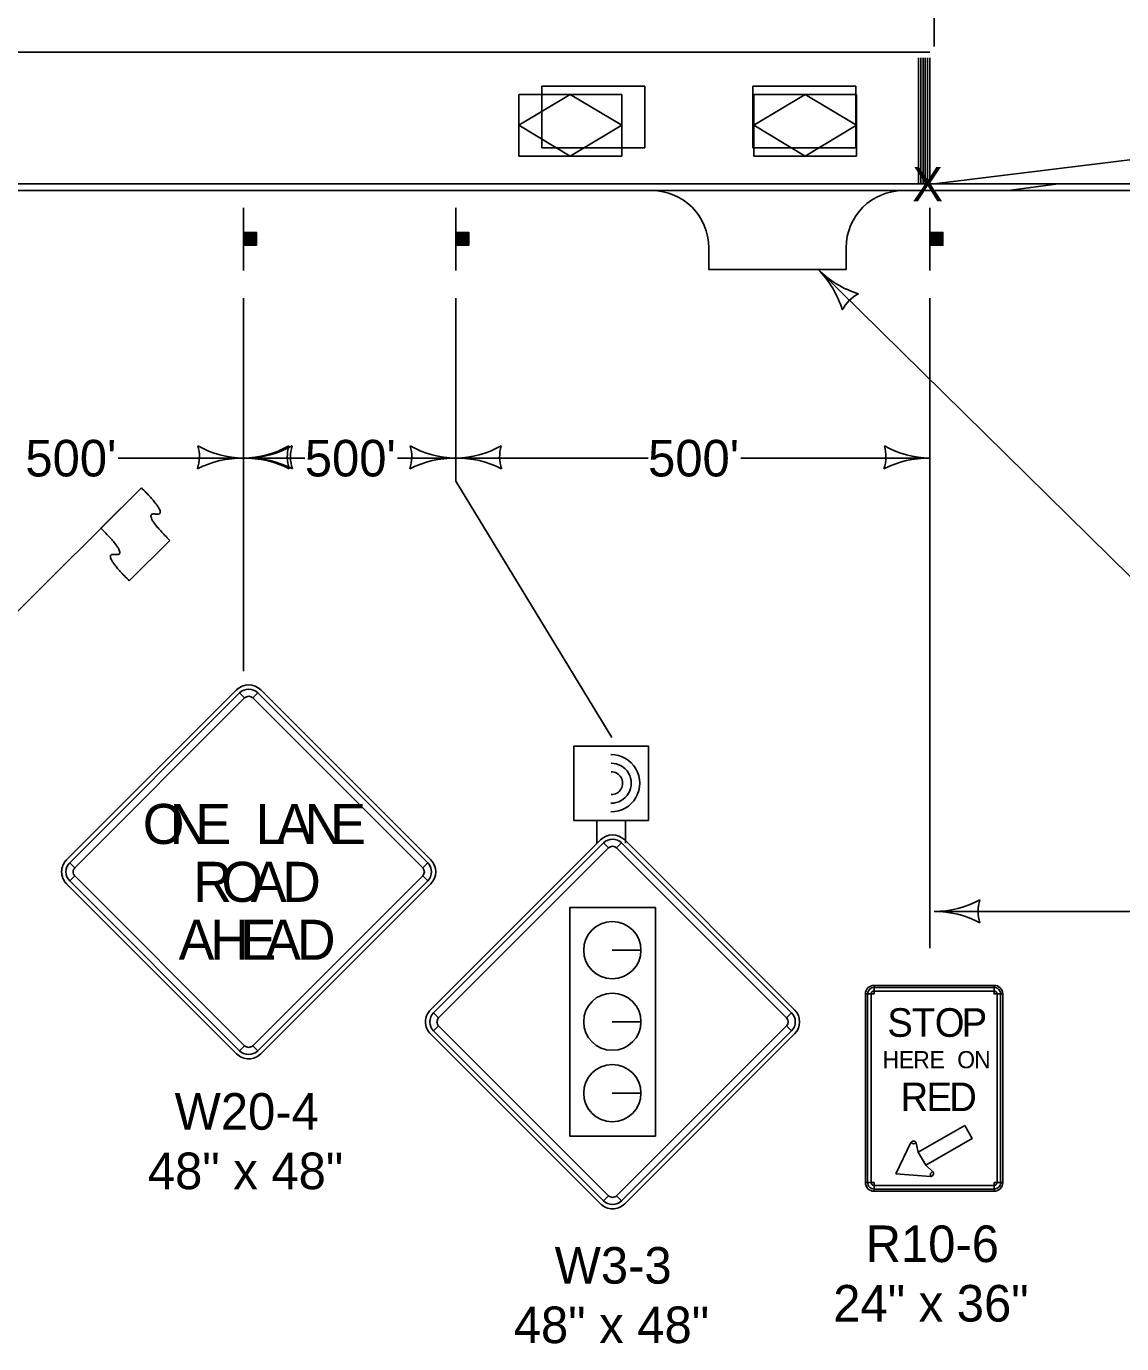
# Model space of a CAD drawing. Extents: x -2134934 to -2122394, y -2140205 to -2137036.
# Drawn here: x -2129927 to -2129448, y -2138172 to -2137596 of the extents above; entities that cross this region are included whole.
import ezdxf

# ---------------------------------------------------------------- set-up
doc = ezdxf.new("R2010")
doc.units = 0
for name, color, linetype in [('Barrier', 7, 'Continuous'), ('BridgeSuperStructureExisting', 7, 'Continuous'), ('DsnShtPlotIdentification', 7, 'Continuous'), ('DsnShtPlotShape', 7, 'Continuous'), ('dsnTextFinalPlan', 7, 'Continuous'), ('TC_Barrier', 7, 'Continuous')]:
    doc.layers.add(name, color=color, linetype=linetype)

msp = doc.modelspace()

# ---------------------------------------------------------------- linework, layer by layer
at = {"layer": 'Barrier'}
for p, q in [((-2129933.82, -2137855.42), (-2129876.5, -2137798.11)), ((-2129876.5, -2137798.11), (-2129894.18, -2137815.79)), ((-2129881.8, -2137838.78), (-2129864.12, -2137821.1)), ((-2129834.91, -2137886.48), (-2129909.16, -2137960.72)), ((-2129750.06, -2137960.72), (-2129824.31, -2137886.48)), ((-2129833.59, -2137887.8), (-2129831.38, -2137890.01)), ((-2129827.84, -2137890.01), (-2129825.63, -2137887.8)), ((-2129675.93, -2137952.07), (-2129750.18, -2138026.31)), ((-2129674.61, -2137953.39), (-2129672.4, -2137955.6)), ((-2129668.86, -2137955.6), (-2129666.65, -2137953.39)), ((-2129591.08, -2138026.31), (-2129665.32, -2137952.07)), ((-2129905.62, -2137964.26), (-2129907.83, -2137962.05)), ((-2129751.39, -2137962.05), (-2129753.59, -2137964.26)), ((-2129907.83, -2137970.01), (-2129905.62, -2137967.8)), ((-2129753.59, -2137967.8), (-2129751.39, -2137970.01)), ((-2129909.16, -2137971.33), (-2129834.91, -2138045.58)), ((-2129824.31, -2138045.58), (-2129750.06, -2137971.33)), ((-2129658.22, -2138000.29), (-2129670.72, -2138000.29)), ((-2129670.72, -2138000.29), (-2129658.22, -2138000.29)), ((-2129560.12, -2138019.4), (-2129556.37, -2138019.4)), ((-2129559.18, -2138019.4), (-2129557.62, -2138019.4)), ((-2129556.37, -2138019.4), (-2129556.37, -2138015.65)), ((-2129556.37, -2138018.15), (-2129556.37, -2138016.58)), ((-2129503.87, -2138015.65), (-2129503.87, -2138019.4)), ((-2129503.87, -2138016.58), (-2129503.87, -2138018.15)), ((-2129503.87, -2138019.4), (-2129500.12, -2138019.4)), ((-2129502.62, -2138019.4), (-2129501.05, -2138019.4)), ((-2129746.64, -2138029.85), (-2129748.85, -2138027.64)), ((-2129658.22, -2138031.54), (-2129670.72, -2138031.54)), ((-2129670.72, -2138031.54), (-2129658.22, -2138031.54)), ((-2129592.41, -2138027.64), (-2129594.61, -2138029.85)), ((-2129750.18, -2138036.92), (-2129675.93, -2138111.16)), ((-2129748.85, -2138035.59), (-2129746.64, -2138033.38)), ((-2129665.32, -2138111.16), (-2129591.08, -2138036.92)), ((-2129594.61, -2138033.38), (-2129592.41, -2138035.59)), ((-2129831.38, -2138042.04), (-2129833.59, -2138044.25)), ((-2129825.63, -2138044.25), (-2129827.84, -2138042.04)), ((-2129658.22, -2138062.79), (-2129670.72, -2138062.79)), ((-2129670.72, -2138062.79), (-2129658.22, -2138062.79)), ((-2129540.26, -2138084.38), (-2129539.15, -2138084.96)), ((-2129539.15, -2138084.96), (-2129537.93, -2138084.69)), ((-2129531.65, -2138097.95), (-2129531.7, -2138099.2)), ((-2129530.8, -2138097.03), (-2129531.65, -2138097.95)), ((-2129556.37, -2138101.9), (-2129560.12, -2138101.9)), ((-2129557.62, -2138101.9), (-2129559.18, -2138101.9)), ((-2129556.37, -2138105.65), (-2129556.37, -2138101.9)), ((-2129556.37, -2138104.71), (-2129556.37, -2138103.15)), ((-2129500.12, -2138101.9), (-2129503.87, -2138101.9)), ((-2129503.87, -2138101.9), (-2129503.87, -2138105.65)), ((-2129503.87, -2138103.15), (-2129503.87, -2138104.71)), ((-2129501.05, -2138101.9), (-2129502.62, -2138101.9)), ((-2129672.4, -2138107.63), (-2129674.61, -2138109.84)), ((-2129666.65, -2138109.84), (-2129668.86, -2138107.63))]:
    msp.add_line(p, q, dxfattribs=at)
for points in [[(-2129833.59, -2137887.8), (-2129907.83, -2137962.05), (-2129905.62, -2137964.26), (-2129831.38, -2137890.01), (-2129833.59, -2137887.8)], [(-2129751.39, -2137962.05), (-2129825.63, -2137887.8), (-2129827.84, -2137890.01), (-2129753.59, -2137964.26), (-2129751.39, -2137962.05)], [(-2129674.61, -2137953.39), (-2129748.85, -2138027.64), (-2129746.64, -2138029.85), (-2129672.4, -2137955.6), (-2129674.61, -2137953.39)], [(-2129592.41, -2138027.64), (-2129666.65, -2137953.39), (-2129668.86, -2137955.6), (-2129594.61, -2138029.85), (-2129592.41, -2138027.64)], [(-2129907.83, -2137970.01), (-2129833.59, -2138044.25), (-2129831.38, -2138042.04), (-2129905.62, -2137967.8), (-2129907.83, -2137970.01)], [(-2129825.63, -2138044.25), (-2129751.39, -2137970.01), (-2129753.59, -2137967.8), (-2129827.84, -2138042.04), (-2129825.63, -2138044.25)], [(-2129651.9, -2137981.67), (-2129689.36, -2137981.67), (-2129689.36, -2138081.56), (-2129651.9, -2138081.56), (-2129651.9, -2137981.67)], [(-2129556.37, -2138105.65), (-2129503.87, -2138105.65), (-2129503.87, -2138101.9), (-2129500.12, -2138101.9), (-2129500.12, -2138019.4), (-2129503.87, -2138019.4), (-2129503.87, -2138015.65), (-2129556.37, -2138015.65), (-2129556.37, -2138019.4), (-2129560.12, -2138019.4), (-2129560.12, -2138101.9), (-2129556.37, -2138101.9), (-2129556.37, -2138105.65)], [(-2129557.62, -2138019.4), (-2129557.62, -2138101.9), (-2129559.18, -2138101.9), (-2129559.18, -2138019.4), (-2129557.62, -2138019.4)], [(-2129503.87, -2138018.15), (-2129556.37, -2138018.15), (-2129556.37, -2138016.58), (-2129503.87, -2138016.58), (-2129503.87, -2138018.15)], [(-2129502.62, -2138101.9), (-2129502.62, -2138019.4), (-2129501.05, -2138019.4), (-2129501.05, -2138101.9), (-2129502.62, -2138101.9)], [(-2129748.85, -2138035.59), (-2129674.61, -2138109.84), (-2129672.4, -2138107.63), (-2129746.64, -2138033.38), (-2129748.85, -2138035.59)], [(-2129666.65, -2138109.84), (-2129592.41, -2138035.59), (-2129594.61, -2138033.38), (-2129668.86, -2138107.63), (-2129666.65, -2138109.84)], [(-2129516.74, -2138076.9), (-2129513.46, -2138082.58), (-2129533.77, -2138094.3), (-2129537.05, -2138088.62), (-2129516.74, -2138076.9)], [(-2129546.77, -2138098.02), (-2129531.7, -2138099.2), (-2129531.65, -2138097.95), (-2129530.8, -2138097.03), (-2129533.77, -2138094.3), (-2129537.05, -2138088.62), (-2129537.93, -2138084.69), (-2129539.15, -2138084.96), (-2129540.26, -2138084.38), (-2129546.77, -2138098.02)], [(-2129556.37, -2138103.15), (-2129503.87, -2138103.15), (-2129503.87, -2138104.71), (-2129556.37, -2138104.71), (-2129556.37, -2138103.15)]]:
    msp.add_lwpolyline(points, close=True, dxfattribs=at)
for centre in [(-2129670.72, -2138000.29), (-2129670.72, -2138031.54), (-2129670.72, -2138062.79)]:
    msp.add_circle(centre, 12.5, dxfattribs=at)
for centre, radius, start, end in [((-2129829.61, -2137891.78), 7.5, 44.99999, 134.99974), ((-2129829.61, -2137891.78), 5.62, 44.99999, 134.99974), ((-2129829.61, -2137891.78), 2.5, 44.99999, 134.99974), ((-2129670.63, -2137957.37), 7.5, 44.99999, 134.99974), ((-2129670.63, -2137957.37), 5.62, 44.99999, 134.99974), ((-2129670.63, -2137957.37), 2.5, 44.99999, 134.99974), ((-2129903.85, -2137966.03), 7.5, 134.99974, 224.99995), ((-2129903.85, -2137966.03), 5.62, 134.99974, 224.99995), ((-2129755.36, -2137966.03), 5.62, 315.00016, 44.9998), ((-2129755.36, -2137966.03), 7.5, 315.00016, 44.9998), ((-2129903.85, -2137966.03), 2.5, 134.99974, 224.99995), ((-2129755.36, -2137966.03), 2.5, 315.00016, 44.9998), ((-2129556.37, -2138019.4), 3.75, 90.00021, 179.99985), ((-2129556.37, -2138019.4), 2.81, 90.00021, 179.99985), ((-2129556.37, -2138019.4), 1.25, 90.00021, 179.99985), ((-2129503.87, -2138019.4), 3.75, 0, 90.00021), ((-2129503.87, -2138019.4), 2.81, 0, 90.00021), ((-2129503.87, -2138019.4), 1.25, 0, 90.00021), ((-2129744.87, -2138031.62), 7.5, 134.99974, 224.99995), ((-2129744.87, -2138031.62), 5.62, 134.99974, 224.99995), ((-2129744.87, -2138031.62), 2.5, 134.99974, 224.99995), ((-2129596.38, -2138031.62), 2.5, 315.00016, 44.9998), ((-2129596.38, -2138031.62), 5.62, 315.00016, 44.9998), ((-2129596.38, -2138031.62), 7.5, 315.00016, 44.9998), ((-2129829.61, -2138040.27), 2.5, 224.99995, 315.00016), ((-2129829.61, -2138040.27), 7.5, 224.99995, 315.00016), ((-2129829.61, -2138040.27), 5.62, 224.99995, 315.00016), ((-2129539.15, -2138084.96), 1.25, 12.62232, 152.27557), ((-2129531.65, -2138097.95), 1.25, 267.72427, 47.37758), ((-2129556.37, -2138101.9), 3.75, 179.99985, 270.00006), ((-2129556.37, -2138101.9), 2.81, 179.99985, 270.00006), ((-2129556.37, -2138101.9), 1.25, 179.99985, 270.00006), ((-2129503.87, -2138101.9), 3.75, 270.00006, 0.00027), ((-2129503.87, -2138101.9), 2.81, 270.00006, 0.00027), ((-2129503.87, -2138101.9), 1.25, 270.00006, 0.00027), ((-2129670.63, -2138105.86), 7.5, 224.99995, 315.00016), ((-2129670.63, -2138105.86), 5.62, 224.99995, 315.00016), ((-2129670.63, -2138105.86), 2.5, 224.99995, 315.00016)]:
    msp.add_arc(centre, radius, start, end, dxfattribs=at)
for points in [[(-2129864.12, -2137821.1), (-2129876.5, -2137808.72), (-2129864.12, -2137810.49), (-2129876.5, -2137798.11)], [(-2129894.18, -2137815.79), (-2129881.8, -2137828.17), (-2129894.17, -2137826.4), (-2129881.8, -2137838.78)]]:
    msp.add_open_spline(points, degree=2, dxfattribs=at)
at = {"layer": 'BridgeSuperStructureExisting'}
for p, q in [((-2129530.12, -2137367.55), (-2129530.12, -2137605.16)), ((-2129530.12, -2137665.16), (-2129039.8, -2137605.17)), ((-2129536.95, -2137665.16), (-2129536.95, -2137610.16)), ((-2129535.95, -2137665.16), (-2129535.95, -2137610.16)), ((-2129534.95, -2137665.16), (-2129534.95, -2137610.16)), ((-2129533.95, -2137665.16), (-2129533.95, -2137610.16)), ((-2129532.95, -2137665.16), (-2129532.95, -2137610.16)), ((-2129531.95, -2137665.16), (-2129531.95, -2137610.16)), ((-2129701.47, -2137622.46), (-2129656.47, -2137622.46)), ((-2129701.47, -2137649.46), (-2129701.47, -2137622.46)), ((-2129656.47, -2137622.46), (-2129701.47, -2137622.46)), ((-2129701.47, -2137622.46), (-2129701.47, -2137649.46)), ((-2129656.47, -2137622.46), (-2129656.47, -2137649.46)), ((-2129656.47, -2137649.46), (-2129656.47, -2137622.46)), ((-2129609.28, -2137622.54), (-2129564.28, -2137622.54)), ((-2129609.28, -2137649.54), (-2129609.28, -2137622.54)), ((-2129564.28, -2137622.54), (-2129609.28, -2137622.54)), ((-2129609.28, -2137622.54), (-2129609.28, -2137649.54)), ((-2129564.28, -2137622.54), (-2129564.28, -2137649.54)), ((-2129564.28, -2137649.54), (-2129564.28, -2137622.54)), ((-2129711.63, -2137653.13), (-2129711.63, -2137626.13)), ((-2129711.63, -2137626.13), (-2129666.63, -2137626.13)), ((-2129666.63, -2137653.13), (-2129666.63, -2137626.13)), ((-2129608.95, -2137653.13), (-2129608.95, -2137626.13)), ((-2129608.95, -2137626.13), (-2129563.95, -2137626.13)), ((-2129563.95, -2137653.13), (-2129563.95, -2137626.13)), ((-2129656.47, -2137649.46), (-2129701.47, -2137649.46)), ((-2129701.47, -2137649.46), (-2129656.47, -2137649.46)), ((-2129564.28, -2137649.54), (-2129609.28, -2137649.54)), ((-2129609.28, -2137649.54), (-2129564.28, -2137649.54)), ((-2129711.63, -2137653.13), (-2129666.63, -2137653.13)), ((-2129608.95, -2137653.13), (-2129563.95, -2137653.13)), ((-2130182.57, -2137665.16), (-2128870.12, -2137665.16)), ((-2129543.56, -2137668.16), (-2129653.56, -2137668.16)), ((-2129639.46, -2137668.16), (-2129614.46, -2137668.16)), ((-2129831.95, -2137675.66), (-2129831.95, -2137703.16)), ((-2129739.15, -2137675.66), (-2129739.15, -2137703.16)), ((-2129531.95, -2137675.66), (-2129531.95, -2137703.16)), ((-2129831.54, -2137692.11), (-2129831.54, -2137686.52)), ((-2129831.26, -2137686.52), (-2129831.26, -2137692.11)), ((-2129830.99, -2137692.11), (-2129830.99, -2137686.52)), ((-2129830.73, -2137686.52), (-2129830.73, -2137692.11)), ((-2129830.51, -2137692.11), (-2129830.51, -2137686.52)), ((-2129830.3, -2137686.52), (-2129830.3, -2137692.11)), ((-2129829.96, -2137692.11), (-2129829.96, -2137686.52)), ((-2129829.7, -2137686.52), (-2129829.7, -2137692.11)), ((-2129829.47, -2137692.11), (-2129829.49, -2137686.52)), ((-2129829.16, -2137686.52), (-2129829.16, -2137692.11)), ((-2129828.78, -2137692.11), (-2129828.78, -2137686.52)), ((-2129828.35, -2137686.52), (-2129828.35, -2137692.11)), ((-2129828.12, -2137692.11), (-2129828.14, -2137686.52)), ((-2129827.71, -2137686.52), (-2129827.69, -2137692.11)), ((-2129827.49, -2137692.11), (-2129827.49, -2137686.52)), ((-2129827.17, -2137686.52), (-2129827.17, -2137692.11)), ((-2129826.94, -2137692.11), (-2129826.94, -2137686.52)), ((-2129826.62, -2137686.52), (-2129826.62, -2137692.11)), ((-2129738.74, -2137692.11), (-2129738.74, -2137686.52)), ((-2129738.46, -2137686.52), (-2129738.46, -2137692.11)), ((-2129738.2, -2137692.11), (-2129738.2, -2137686.52)), ((-2129737.93, -2137686.52), (-2129737.93, -2137692.11)), ((-2129737.71, -2137692.11), (-2129737.71, -2137686.52)), ((-2129737.5, -2137686.52), (-2129737.5, -2137692.11)), ((-2129737.16, -2137692.11), (-2129737.16, -2137686.52)), ((-2129736.9, -2137686.52), (-2129736.9, -2137692.11)), ((-2129736.68, -2137692.11), (-2129736.7, -2137686.52)), ((-2129736.36, -2137686.52), (-2129736.36, -2137692.11)), ((-2129735.98, -2137692.11), (-2129735.98, -2137686.52)), ((-2129735.55, -2137686.52), (-2129735.55, -2137692.11)), ((-2129735.33, -2137692.11), (-2129735.35, -2137686.52)), ((-2129734.91, -2137686.52), (-2129734.9, -2137692.11)), ((-2129734.69, -2137692.11), (-2129734.69, -2137686.52)), ((-2129734.37, -2137686.52), (-2129734.37, -2137692.11)), ((-2129734.15, -2137692.11), (-2129734.15, -2137686.52)), ((-2129733.83, -2137686.52), (-2129733.83, -2137692.11)), ((-2129531.54, -2137692.11), (-2129531.54, -2137686.52)), ((-2129531.26, -2137686.52), (-2129531.26, -2137692.11)), ((-2129530.99, -2137692.11), (-2129530.99, -2137686.52)), ((-2129530.73, -2137686.52), (-2129530.73, -2137692.11)), ((-2129530.51, -2137692.11), (-2129530.51, -2137686.52)), ((-2129530.3, -2137686.52), (-2129530.3, -2137692.11)), ((-2129529.96, -2137692.11), (-2129529.96, -2137686.52)), ((-2129529.7, -2137686.52), (-2129529.7, -2137692.11)), ((-2129529.48, -2137692.11), (-2129529.49, -2137686.52)), ((-2129529.16, -2137686.52), (-2129529.16, -2137692.11)), ((-2129528.78, -2137692.11), (-2129528.78, -2137686.52)), ((-2129528.35, -2137686.52), (-2129528.35, -2137692.11)), ((-2129528.13, -2137692.11), (-2129528.14, -2137686.52)), ((-2129527.71, -2137686.52), (-2129527.69, -2137692.11)), ((-2129527.49, -2137692.11), (-2129527.49, -2137686.52)), ((-2129527.17, -2137686.52), (-2129527.17, -2137692.11)), ((-2129526.94, -2137692.11), (-2129526.94, -2137686.52)), ((-2129526.63, -2137686.52), (-2129526.63, -2137692.11)), ((-2129366.79, -2137913.4), (-2129580.78, -2137702.65)), ((-2129831.95, -2137878.33), (-2129831.95, -2137715.16)), ((-2129739.15, -2137795.16), (-2129739.15, -2137715.16)), ((-2129531.95, -2137999.46), (-2129531.95, -2137715.16)), ((-2129886.7, -2137785.16), (-2129831.95, -2137785.16)), ((-2129830.55, -2137785.16), (-2129805.1, -2137785.16)), ((-2129764.6, -2137785.16), (-2129739.15, -2137785.16)), ((-2129739.15, -2137785.16), (-2129655.1, -2137785.16)), ((-2129614.6, -2137785.16), (-2129531.95, -2137785.16)), ((-2129739.15, -2137795.16), (-2129670.96, -2137907.34)), ((-2129677.47, -2137943.52), (-2129677.47, -2137953.52)), ((-2129664.97, -2137943.52), (-2129664.97, -2137953.52)), ((-2128866.54, -2137983.33), (-2129530.12, -2137983.33))]:
    msp.add_line(p, q, dxfattribs=at)
for points in [[(-2129831.86, -2137692.11), (-2129831.86, -2137686.48), (-2129826.23, -2137686.48), (-2129826.23, -2137692.11)], [(-2129739.06, -2137692.11), (-2129739.06, -2137686.48), (-2129733.43, -2137686.48), (-2129733.43, -2137692.11)], [(-2129531.86, -2137692.11), (-2129531.86, -2137686.48), (-2129526.23, -2137686.48), (-2129526.23, -2137692.11)], [(-2129687.47, -2137943.52), (-2129687.47, -2137911.02), (-2129654.97, -2137911.02), (-2129654.97, -2137943.52)]]:
    msp.add_lwpolyline(points, close=True, dxfattribs=at)
msp.add_lwpolyline([(-2129628.56, -2137693.16), (-2129628.56, -2137702.65), (-2129568.56, -2137702.65), (-2129568.56, -2137693.16)], dxfattribs=at)
for centre, radius, start, end in [((-2129653.56, -2137693.16), 25, 0, 90), ((-2129543.56, -2137693.16), 25, 90, 180), ((-2129867.57, -2137784.54), 16.42, 341.26665, 16.73335), ((-2129831.2, -2137742.67), 42.5, 240.92751, 268.9824), ((-2129832.71, -2137742.67), 42.5, 271.0176, 299.07249), ((-2129831.31, -2137742.67), 42.5, 271.0176, 299.07249), ((-2129796.33, -2137784.54), 16.42, 163.26665, 198.73335), ((-2129794.94, -2137784.54), 16.42, 163.26665, 198.73335), ((-2129774.77, -2137784.54), 16.42, 341.26665, 16.73335), ((-2129738.4, -2137742.67), 42.5, 240.92751, 268.9824), ((-2129739.91, -2137742.67), 42.5, 271.0176, 299.07249), ((-2129703.54, -2137784.54), 16.42, 163.26665, 198.73335), ((-2129567.57, -2137784.54), 16.42, 341.26665, 16.73335), ((-2129531.2, -2137742.67), 42.5, 240.92751, 268.9824), ((-2129832.68, -2137827.65), 42.5, 89.0176, 117.07249), ((-2129831.22, -2137827.65), 42.5, 62.92751, 90.9824), ((-2129829.83, -2137827.65), 42.5, 62.92751, 90.9824), ((-2129739.88, -2137827.65), 42.5, 89.0176, 117.07249), ((-2129738.42, -2137827.65), 42.5, 62.92751, 90.9824), ((-2129532.68, -2137827.65), 42.5, 89.0176, 117.07249), ((-2129671.21, -2137927.28), 12.5, 269.40414, 90.54446), ((-2129671.21, -2137927.28), 12.5, 269.40414, 90.54446), ((-2129671.21, -2137927.28), 8.75, 269.40414, 90.54446), ((-2129671.21, -2137927.28), 5, 269.40414, 90.54446)]:
    msp.add_arc(centre, radius, start, end, dxfattribs=at)
at = {"layer": 'DsnShtPlotIdentification'}
for p, q in [((-2129531.95, -2137607.66), (-2130184.45, -2137607.66)), ((-2129535.12, -2137665.16), (-2130182.57, -2137665.16)), ((-2130182.57, -2137668.16), (-2129497.55, -2137668.16)), ((-2130181.95, -2137665.16), (-2128681.95, -2137665.16)), ((-2129475.87, -2137665.16), (-2129530.12, -2137665.16)), ((-2129497.55, -2137668.16), (-2129475.87, -2137665.16)), ((-2129475.87, -2137665.16), (-2129497.55, -2137668.16)), ((-2129497.55, -2137668.16), (-2129183.89, -2137668.16)), ((-2129182.92, -2137665.16), (-2129475.87, -2137665.16))]:
    msp.add_line(p, q, dxfattribs=at)
for points in [[(-2128870.12, -2137665.16), (-2130182.57, -2137665.16)], [(-2128870.12, -2137668.16), (-2130182.57, -2137668.16)], [(-2129532.12, -2137665.16), (-2129533.12, -2137665.16), (-2129534.12, -2137665.16), (-2129535.12, -2137665.16)], [(-2129530.12, -2137665.16), (-2129531.12, -2137665.16), (-2129532.12, -2137665.16)]]:
    msp.add_lwpolyline(points, dxfattribs=at)
at = {"layer": 'DsnShtPlotShape'}
for centre, radius, start, end in [((-2129610.97, -2137732.56), 42.5, 16.65786, 44.73035), ((-2129550.58, -2137672.74), 42.5, 224.73035, 252.80284), ((-2129555.7, -2137727.96), 16.42, 116.997, 152.46371), ((-2129530.12, -2137940.83), 42.5, 270, 298.07249), ((-2129494.48, -2137983.33), 16.42, 162.26665, 197.73335), ((-2129530.12, -2138025.83), 42.5, 61.92751, 90)]:
    msp.add_arc(centre, radius, start, end, dxfattribs=at)
at = {"layer": 'dsnTextFinalPlan'}
for points in [[(-2129711.63, -2137639.63), (-2129689.13, -2137626.13), (-2129666.63, -2137639.63), (-2129689.13, -2137653.13)], [(-2129608.95, -2137639.63), (-2129586.45, -2137626.13), (-2129563.95, -2137639.63), (-2129586.45, -2137653.13)]]:
    msp.add_lwpolyline(points, close=True, dxfattribs=at)
at = {"layer": 'TC_Barrier'}
msp.add_line((-2129864.12, -2137821.1), (-2129881.8, -2137838.78), dxfattribs=at)
for points in [[(-2129876.5, -2137798.11), (-2129864.12, -2137810.49), (-2129876.5, -2137808.72), (-2129864.12, -2137821.1)], [(-2129894.18, -2137815.79), (-2129881.8, -2137828.17), (-2129894.17, -2137826.4), (-2129881.8, -2137838.78)]]:
    msp.add_open_spline(points, degree=2, dxfattribs=at)

# ---------------------------------------------------------------- texts
at = {"layer": 'Barrier'}
for s, height, p in [('O', 17.5, (-2129875.89, -2137953.84)), ('N', 17.5, (-2129864.12, -2137953.84)), ('E', 17.5, (-2129852.89, -2137953.84)), ('L', 17.5, (-2129826.64, -2137953.84)), ('A', 17.5, (-2129817.44, -2137953.84)), ('N', 17.5, (-2129805.18, -2137953.84)), ('E', 17.5, (-2129793.95, -2137953.84)), ('R', 17.5, (-2129853.79, -2137979.15)), ('O', 17.5, (-2129841.5, -2137979.15)), ('A', 17.5, (-2129828.66, -2137979.15)), ('D', 17.5, (-2129815, -2137979.15)), ('A', 17.5, (-2129860.22, -2138004.47)), ('H', 17.5, (-2129846.36, -2138004.47)), ('E', 17.5, (-2129833.14, -2138004.47)), ('A', 17.5, (-2129822.43, -2138004.47)), ('D', 17.5, (-2129808.56, -2138004.47)), ('S', 12.5, (-2129550.56, -2138038.15)), ('T', 12.5, (-2129539.8, -2138038.15)), ('O', 12.5, (-2129529.81, -2138038.15)), ('P', 12.5, (-2129518.07, -2138038.15)), ('H', 7.5, (-2129552.64, -2138051.9)), ('E', 7.5, (-2129545.49, -2138051.9)), ('R', 7.5, (-2129539.23, -2138051.9)), ('E', 7.5, (-2129532.08, -2138051.9)), ('O', 7.5, (-2129520.01, -2138051.9)), ('N', 7.5, (-2129512.63, -2138051.9)), ('R', 12.5, (-2129544.8, -2138070.65)), ('E', 12.5, (-2129533.47, -2138070.65)), ('D', 12.5, (-2129523.51, -2138070.65)), ('W20-4', 16, (-2129861.97, -2138078.77)), ('48" x 48"', 16, (-2129873.68, -2138104.77)), ('R10-6', 16, (-2129560.04, -2138136.65)), ('W3-3', 16, (-2129695.92, -2138146.08)), ('24" x 36"', 16, (-2129574.18, -2138162.65)), ('48" x 48"', 16, (-2129713.8, -2138172.08))]:
    msp.add_text(s, height=height, dxfattribs=at).set_placement(p)
at = {"layer": 'BridgeSuperStructureExisting'}
for s, height, p in [('X', 15, (-2129539.63, -2137672.81)), ("500'", 16, (-2129927.2, -2137793.16)), ("500'", 16, (-2129805.1, -2137793.16)), ("500'", 16, (-2129655.1, -2137793.16))]:
    msp.add_text(s, height=height, dxfattribs=at).set_placement(p)

doc.saveas('drawing.dxf')
